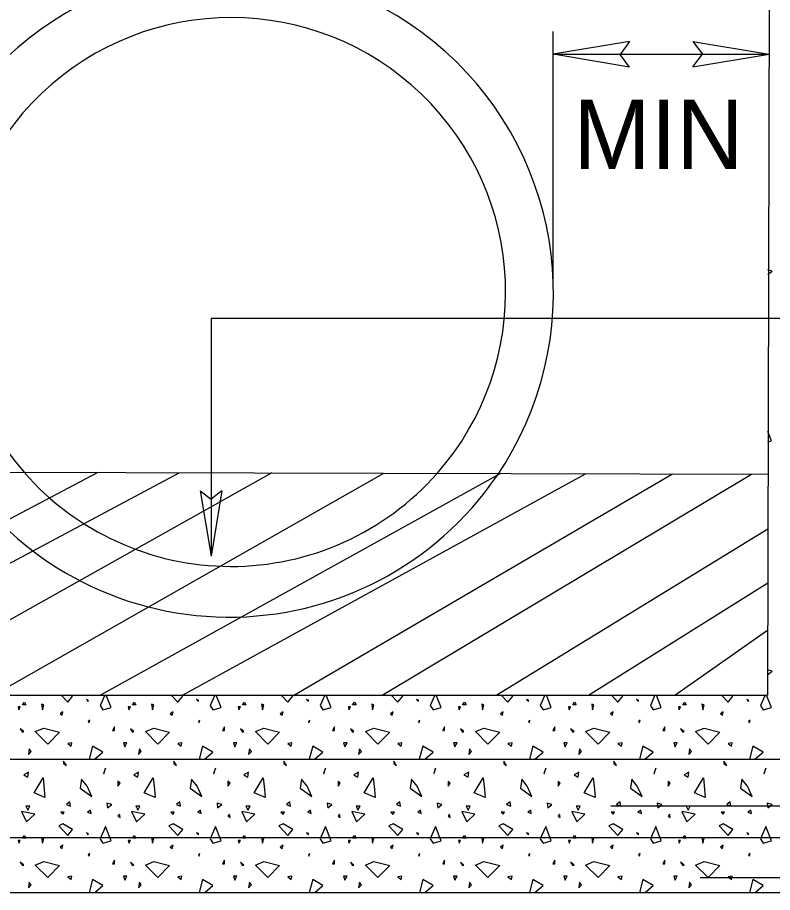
# Model space of a CAD drawing. Extents: x 9.6 to 16.8, y 2.2 to 12.2.
# Drawn here: x 15.328 to 15.979, y 6.99 to 7.746 of the extents above; entities that cross this region are included whole.
import ezdxf

# ---------------------------------------------------------------- set-up
doc = ezdxf.new("R2010")
doc.units = 0
for name, color, linetype in [('DETL-DIMS', 7, 'Continuous'), ('DETL-LINE', 7, 'Continuous'), ('DETL-NOTE', 7, 'Continuous'), ('DETL-PATT', 7, 'Continuous')]:
    doc.layers.add(name, color=color, linetype=linetype)

msp = doc.modelspace()

# ---------------------------------------------------------------- linework, layer by layer
at = {"layer": 'DETL-DIMS'}
for p, q in [((15.79012, 7.51631), (15.79012, 7.73388)), ((15.85604, 7.72498), (15.79012, 7.71412)), ((15.85604, 7.72498), (15.84776, 7.714)), ((15.91067, 7.72522), (15.97651, 7.71412)), ((15.91067, 7.72522), (15.91886, 7.71424)), ((15.79012, 7.71412), (15.97651, 7.71412)), ((15.85596, 7.70302), (15.79012, 7.71412)), ((15.85596, 7.70302), (15.84776, 7.714)), ((15.91059, 7.70325), (15.91886, 7.71424)), ((15.91059, 7.70325), (15.97651, 7.71412)), ((16.21412, 7.48596), (15.49467, 7.48596)), ((15.49467, 7.48596), (15.49467, 7.28039)), ((15.48525, 7.33686), (15.49467, 7.28039)), ((15.48525, 7.33686), (15.49467, 7.3298)), ((15.50408, 7.33686), (15.49467, 7.28039)), ((15.50408, 7.33686), (15.49467, 7.3298))]:
    msp.add_line(p, q, dxfattribs=at)
at = {"layer": 'DETL-LINE'}
for p, q in [((15.9791, 8.70102), (15.97506, 7.16059)), ((15.03792, 7.35373), (15.97557, 7.35125)), ((15.03486, 7.16059), (15.97506, 7.16059)), ((14.98871, 7.10522), (16.01604, 7.10522)), ((15.99635, 7.06451), (15.83973, 7.06451)), ((14.90416, 7.03737), (16.09322, 7.03737)), ((16.07349, 7.00275), (15.91686, 7.00275)), ((14.84702, 6.99), (16.1489, 6.99))]:
    msp.add_line(p, q, dxfattribs=at)
for centre, radius, start, end in [((15.51033, 7.50778), 0.27991, 325.61931, 213.35871), ((15.51198, 7.50873), 0.23705, 318.61489, 221.08317), ((15.51033, 7.50778), 0.27991, 213.35871, 325.61931), ((15.51198, 7.50873), 0.23705, 221.08317, 318.61489)]:
    msp.add_arc(centre, radius, start, end, dxfattribs=at)
at = {"layer": 'DETL-PATT'}
for p, q in [((15.39698, 7.35278), (15.03486, 7.16235)), ((15.10784, 7.16059), (15.46718, 7.35259)), ((15.54729, 7.35239), (15.20498, 7.16059)), ((15.30702, 7.16059), (15.64373, 7.35212)), ((15.74463, 7.35188), (15.39937, 7.16059)), ((15.47004, 7.16059), (15.81784, 7.35169)), ((15.89294, 7.35149), (15.56678, 7.16059)), ((15.64231, 7.16059), (15.96133, 7.35129)), ((15.97545, 7.304), (15.74133, 7.16059)), ((15.82059, 7.16059), (15.97529, 7.25757)), ((15.89498, 7.16059), (15.97522, 7.21659))]:
    msp.add_line(p, q, dxfattribs=at)
for points in [[(15.97549, 7.52384), (15.97898, 7.52678), (15.97549, 7.52776)], [(15.97533, 7.37929), (15.97843, 7.38008), (15.97533, 7.38816)], [(15.9751, 7.18094), (15.97545, 7.1782), (15.97898, 7.18118), (15.9751, 7.18227)], [(15.36525, 7.16059), (15.37094, 7.15451), (15.37518, 7.15973), (15.37369, 7.16059)], [(15.4029, 7.16059), (15.3989, 7.15153), (15.40129, 7.14784), (15.40835, 7.14969), (15.40416, 7.16059)], [(15.46027, 7.16059), (15.46596, 7.15451), (15.4702, 7.15973), (15.46871, 7.16059)], [(15.49792, 7.16059), (15.49392, 7.15153), (15.49631, 7.14784), (15.50337, 7.14969), (15.49918, 7.16059)], [(15.55529, 7.16059), (15.56098, 7.15451), (15.56522, 7.15973), (15.56373, 7.16059)], [(15.5929, 7.16059), (15.58894, 7.15153), (15.59133, 7.14784), (15.59839, 7.14969), (15.59416, 7.16059)], [(15.65031, 7.16059), (15.656, 7.15451), (15.66024, 7.15973), (15.65875, 7.16059)], [(15.68792, 7.16059), (15.68392, 7.15153), (15.68635, 7.14784), (15.69341, 7.14969), (15.68918, 7.16059)], [(15.74529, 7.16059), (15.75098, 7.15451), (15.75522, 7.15973), (15.75373, 7.16059)], [(15.78294, 7.16059), (15.77894, 7.15153), (15.78133, 7.14784), (15.78839, 7.14969), (15.7842, 7.16059)], [(15.84031, 7.16059), (15.846, 7.15451), (15.85024, 7.15973), (15.84875, 7.16059)], [(15.87796, 7.16059), (15.87396, 7.15153), (15.87635, 7.14784), (15.88341, 7.14969), (15.87922, 7.16059)], [(15.93533, 7.16059), (15.94102, 7.15451), (15.94525, 7.15973), (15.94376, 7.16059)], [(15.97298, 7.16059), (15.96898, 7.15153), (15.97137, 7.14784), (15.97843, 7.14969), (15.97424, 7.16059)], [(15.39427, 6.99), (15.40129, 6.99596), (15.39239, 7.00118), (15.38949, 6.99)], [(15.48925, 6.99), (15.49631, 6.99596), (15.48741, 7.00118), (15.48451, 6.99)], [(15.58427, 6.99), (15.59133, 6.99596), (15.58243, 7.00118), (15.57949, 6.99)], [(15.67929, 6.99), (15.68635, 6.99596), (15.67745, 7.00118), (15.67451, 6.99)], [(15.77431, 6.99), (15.78133, 6.99596), (15.77247, 7.00118), (15.76953, 6.99)], [(15.86933, 6.99), (15.87635, 6.99596), (15.86745, 7.00118), (15.86455, 6.99)], [(15.96431, 6.99), (15.97137, 6.99596), (15.96247, 7.00118), (15.95957, 6.99)]]:
    msp.add_lwpolyline(points, dxfattribs=at)
for points in [[(15.33353, 7.15451), (15.33482, 7.15208), (15.33184, 7.15208)], [(15.34835, 7.15267), (15.34906, 7.14784), (15.3502, 7.15208)], [(15.38875, 7.1562), (15.38706, 7.15675), (15.38875, 7.15506)], [(15.42855, 7.15451), (15.4298, 7.15208), (15.42686, 7.15208)], [(15.44337, 7.15267), (15.44408, 7.14784), (15.44522, 7.15208)], [(15.48376, 7.1562), (15.48204, 7.15675), (15.48376, 7.15506)], [(15.52357, 7.15451), (15.52482, 7.15208), (15.52188, 7.15208)], [(15.53839, 7.15267), (15.5391, 7.14784), (15.54024, 7.15208)], [(15.57875, 7.1562), (15.57706, 7.15675), (15.57875, 7.15506)], [(15.61859, 7.15451), (15.61984, 7.15208), (15.61686, 7.15208)], [(15.63341, 7.15267), (15.63412, 7.14784), (15.63522, 7.15208)], [(15.67376, 7.1562), (15.67208, 7.15675), (15.67376, 7.15506)], [(15.71357, 7.15451), (15.71486, 7.15208), (15.71188, 7.15208)], [(15.72839, 7.15267), (15.7291, 7.14784), (15.73024, 7.15208)], [(15.76878, 7.1562), (15.7671, 7.15675), (15.76878, 7.15506)], [(15.80859, 7.15451), (15.80988, 7.15208), (15.8069, 7.15208)], [(15.82341, 7.15267), (15.82412, 7.14784), (15.82525, 7.15208)], [(15.8638, 7.1562), (15.86212, 7.15675), (15.8638, 7.15506)], [(15.90361, 7.15451), (15.90486, 7.15208), (15.90192, 7.15208)], [(15.91843, 7.15267), (15.91914, 7.14784), (15.92027, 7.15208)], [(15.95882, 7.1562), (15.9571, 7.15675), (15.95882, 7.15506)], [(15.32816, 7.15027), (15.32875, 7.14784), (15.33, 7.15027)], [(15.36447, 7.14431), (15.36616, 7.14322), (15.36686, 7.14616)], [(15.42318, 7.15027), (15.42376, 7.14784), (15.42502, 7.15027)], [(15.45945, 7.14431), (15.46118, 7.14322), (15.46188, 7.14616)], [(15.5182, 7.15027), (15.51875, 7.14784), (15.52004, 7.15027)], [(15.55447, 7.14431), (15.55616, 7.14322), (15.55686, 7.14616)], [(15.61322, 7.15027), (15.61376, 7.14784), (15.61506, 7.15027)], [(15.64949, 7.14431), (15.65118, 7.14322), (15.65188, 7.14616)], [(15.70824, 7.15027), (15.70878, 7.14784), (15.71004, 7.15027)], [(15.74451, 7.14431), (15.7462, 7.14322), (15.7469, 7.14616)], [(15.80322, 7.15027), (15.8038, 7.14784), (15.80506, 7.15027)], [(15.83953, 7.14431), (15.84122, 7.14322), (15.84192, 7.14616)], [(15.89824, 7.15027), (15.89882, 7.14784), (15.90008, 7.15027)], [(15.93451, 7.14431), (15.93624, 7.14322), (15.93694, 7.14616)], [(15.39, 7.13898), (15.38875, 7.13784), (15.38945, 7.13655)], [(15.48502, 7.13898), (15.48376, 7.13784), (15.48447, 7.13655)], [(15.58004, 7.13898), (15.57875, 7.13784), (15.57945, 7.13655)], [(15.67506, 7.13898), (15.67376, 7.13784), (15.67447, 7.13655)], [(15.77004, 7.13898), (15.76878, 7.13784), (15.76949, 7.13655)], [(15.86506, 7.13898), (15.8638, 7.13784), (15.86451, 7.13655)], [(15.96008, 7.13898), (15.95882, 7.13784), (15.95953, 7.13655)], [(15.33184, 7.12839), (15.33298, 7.12894), (15.33, 7.13133)], [(15.3502, 7.13192), (15.36388, 7.12839), (15.35373, 7.1182), (15.34298, 7.12894)], [(15.41133, 7.13302), (15.40965, 7.13008), (15.41133, 7.13008)], [(15.42686, 7.12839), (15.428, 7.12894), (15.42502, 7.13133)], [(15.44522, 7.13192), (15.4589, 7.12839), (15.44875, 7.1182), (15.438, 7.12894)], [(15.50635, 7.13302), (15.50463, 7.13008), (15.50635, 7.13008)], [(15.52188, 7.12839), (15.52298, 7.12894), (15.52004, 7.13133)], [(15.54024, 7.13192), (15.55392, 7.12839), (15.54376, 7.1182), (15.53302, 7.12894)], [(15.60133, 7.13302), (15.59965, 7.13008), (15.60133, 7.13008)], [(15.61686, 7.12839), (15.618, 7.12894), (15.61506, 7.13133)], [(15.63522, 7.13192), (15.64894, 7.12839), (15.63875, 7.1182), (15.62804, 7.12894)], [(15.69635, 7.13302), (15.69467, 7.13008), (15.69635, 7.13008)], [(15.71188, 7.12839), (15.71302, 7.12894), (15.71004, 7.13133)], [(15.73024, 7.13192), (15.74392, 7.12839), (15.73376, 7.1182), (15.72306, 7.12894)], [(15.79137, 7.13302), (15.78969, 7.13008), (15.79137, 7.13008)], [(15.8069, 7.12839), (15.80804, 7.12894), (15.80506, 7.13133)], [(15.82525, 7.13192), (15.83894, 7.12839), (15.82878, 7.1182), (15.81804, 7.12894)], [(15.88639, 7.13302), (15.88471, 7.13008), (15.88639, 7.13008)], [(15.90192, 7.12839), (15.90306, 7.12894), (15.90008, 7.13133)], [(15.92027, 7.13192), (15.93396, 7.12839), (15.9238, 7.1182), (15.91306, 7.12894)], [(15.33776, 7.11412), (15.33706, 7.10933), (15.33945, 7.11173)], [(15.37094, 7.11878), (15.37392, 7.11639), (15.37447, 7.11933)], [(15.39412, 7.1051), (15.40129, 7.11114), (15.39239, 7.11639), (15.38945, 7.1051)], [(15.4191, 7.11933), (15.42024, 7.1158), (15.42204, 7.11933)], [(15.43278, 7.11412), (15.43208, 7.10933), (15.43447, 7.11173)], [(15.46596, 7.11878), (15.46894, 7.11639), (15.46949, 7.11933)], [(15.4891, 7.1051), (15.49631, 7.11114), (15.48741, 7.11639), (15.48447, 7.1051)], [(15.51412, 7.11933), (15.51522, 7.1158), (15.51706, 7.11933)], [(15.5278, 7.11412), (15.5271, 7.10933), (15.52949, 7.11173)], [(15.56098, 7.11878), (15.56392, 7.11639), (15.56451, 7.11933)], [(15.58412, 7.1051), (15.59133, 7.11114), (15.58243, 7.11639), (15.57945, 7.1051)], [(15.6091, 7.11933), (15.61024, 7.1158), (15.61208, 7.11933)], [(15.62282, 7.11412), (15.62212, 7.10933), (15.62451, 7.11173)], [(15.656, 7.11878), (15.65894, 7.11639), (15.65953, 7.11933)], [(15.67914, 7.1051), (15.68635, 7.11114), (15.67745, 7.11639), (15.67447, 7.1051)], [(15.70412, 7.11933), (15.70525, 7.1158), (15.7071, 7.11933)], [(15.7178, 7.11412), (15.7171, 7.10933), (15.71953, 7.11173)], [(15.75098, 7.11878), (15.75396, 7.11639), (15.75451, 7.11933)], [(15.77416, 7.1051), (15.78133, 7.11114), (15.77247, 7.11639), (15.76949, 7.1051)], [(15.79914, 7.11933), (15.80027, 7.1158), (15.80212, 7.11933)], [(15.81282, 7.11412), (15.81212, 7.10933), (15.81451, 7.11173)], [(15.846, 7.11878), (15.84898, 7.11639), (15.84953, 7.11933)], [(15.86918, 7.1051), (15.87635, 7.11114), (15.86745, 7.11639), (15.86451, 7.1051)], [(15.89416, 7.11933), (15.89529, 7.1158), (15.8971, 7.11933)], [(15.90784, 7.11412), (15.90714, 7.10933), (15.90953, 7.11173)], [(15.94102, 7.11878), (15.944, 7.11639), (15.94455, 7.11933)], [(15.96416, 7.1051), (15.97137, 7.11114), (15.96247, 7.11639), (15.95953, 7.1051)], [(15.36741, 7.10337), (15.36741, 7.10157), (15.3698, 7.09984)], [(15.40188, 7.09267), (15.40243, 7.09267), (15.40357, 7.09745)], [(15.46243, 7.10337), (15.46243, 7.10157), (15.46482, 7.09984)], [(15.49686, 7.09267), (15.49745, 7.09267), (15.49859, 7.09745)], [(15.55745, 7.10337), (15.55745, 7.10157), (15.55984, 7.09984)], [(15.59188, 7.09267), (15.59247, 7.09267), (15.59357, 7.09745)], [(15.65247, 7.10337), (15.65247, 7.10157), (15.65486, 7.09984)], [(15.6869, 7.09267), (15.68745, 7.09267), (15.68859, 7.09745)], [(15.74745, 7.10337), (15.74745, 7.10157), (15.74988, 7.09984)], [(15.78192, 7.09267), (15.78247, 7.09267), (15.78361, 7.09745)], [(15.84247, 7.10337), (15.84247, 7.10157), (15.84486, 7.09984)], [(15.87694, 7.09267), (15.87749, 7.09267), (15.87863, 7.09745)], [(15.93749, 7.10337), (15.93749, 7.10157), (15.93988, 7.09984)], [(15.97192, 7.09267), (15.97251, 7.09267), (15.97365, 7.09745)], [(15.33298, 7.09153), (15.33651, 7.08969), (15.33706, 7.09392)], [(15.428, 7.09153), (15.43153, 7.08969), (15.43208, 7.09392)], [(15.52298, 7.09153), (15.52651, 7.08969), (15.5271, 7.09392)], [(15.618, 7.09153), (15.62153, 7.08969), (15.62212, 7.09392)], [(15.71302, 7.09153), (15.71655, 7.08969), (15.7171, 7.09392)], [(15.80804, 7.09153), (15.81157, 7.08969), (15.81212, 7.09392)], [(15.90306, 7.09153), (15.90659, 7.08969), (15.90714, 7.09392)], [(15.35075, 7.07898), (15.35133, 7.07192), (15.34188, 7.076), (15.34965, 7.08914)], [(15.38282, 7.08784), (15.38169, 7.08024), (15.39169, 7.07302), (15.38761, 7.08192)], [(15.41427, 7.08616), (15.41427, 7.08192), (15.41612, 7.08431)], [(15.44576, 7.07898), (15.44635, 7.07192), (15.43686, 7.076), (15.44463, 7.08914)], [(15.4778, 7.08784), (15.47671, 7.08024), (15.48671, 7.07302), (15.48263, 7.08192)], [(15.50929, 7.08616), (15.50929, 7.08192), (15.51114, 7.08431)], [(15.54078, 7.07898), (15.54133, 7.07192), (15.53188, 7.076), (15.53965, 7.08914)], [(15.57282, 7.08784), (15.57169, 7.08024), (15.58173, 7.07302), (15.57765, 7.08192)], [(15.60431, 7.08616), (15.60431, 7.08192), (15.60616, 7.08431)], [(15.6358, 7.07898), (15.63635, 7.07192), (15.6269, 7.076), (15.63467, 7.08914)], [(15.66784, 7.08784), (15.66671, 7.08024), (15.67675, 7.07302), (15.67263, 7.08192)], [(15.69933, 7.08616), (15.69933, 7.08192), (15.70118, 7.08431)], [(15.73082, 7.07898), (15.73137, 7.07192), (15.72192, 7.076), (15.72969, 7.08914)], [(15.76286, 7.08784), (15.76173, 7.08024), (15.77176, 7.07302), (15.76765, 7.08192)], [(15.79435, 7.08616), (15.79435, 7.08192), (15.79616, 7.08431)], [(15.8258, 7.07898), (15.82639, 7.07192), (15.81694, 7.076), (15.82471, 7.08914)], [(15.85788, 7.08784), (15.85675, 7.08024), (15.86675, 7.07302), (15.86267, 7.08192)], [(15.88933, 7.08616), (15.88933, 7.08192), (15.89118, 7.08431)], [(15.92082, 7.07898), (15.92141, 7.07192), (15.91192, 7.076), (15.91969, 7.08914)], [(15.95286, 7.08784), (15.95176, 7.08024), (15.96176, 7.07302), (15.95769, 7.08192)], [(15.37278, 7.06839), (15.3698, 7.06596), (15.37333, 7.06471)], [(15.4678, 7.06839), (15.46482, 7.06596), (15.46835, 7.06471)], [(15.56282, 7.06839), (15.55984, 7.06596), (15.56337, 7.06471)], [(15.6578, 7.06839), (15.65486, 7.06596), (15.65839, 7.06471)], [(15.75282, 7.06839), (15.74988, 7.06596), (15.75341, 7.06471)], [(15.84784, 7.06839), (15.84486, 7.06596), (15.84839, 7.06471)], [(15.94286, 7.06839), (15.93988, 7.06596), (15.94341, 7.06471)], [(15.33114, 7.06004), (15.33537, 7.05114), (15.34243, 7.05765)], [(15.33482, 7.06471), (15.33651, 7.06118), (15.33835, 7.06471)], [(15.38816, 7.05949), (15.39114, 7.0582), (15.39059, 7.06118)], [(15.40482, 7.0671), (15.40541, 7.06302), (15.40894, 7.06596)], [(15.42616, 7.06004), (15.43039, 7.05114), (15.43745, 7.05765)], [(15.4298, 7.06471), (15.43153, 7.06118), (15.43333, 7.06471)], [(15.48318, 7.05949), (15.48616, 7.0582), (15.48557, 7.06118)], [(15.49984, 7.0671), (15.50039, 7.06302), (15.50392, 7.06596)], [(15.52118, 7.06004), (15.52541, 7.05114), (15.53247, 7.05765)], [(15.52482, 7.06471), (15.52651, 7.06118), (15.52835, 7.06471)], [(15.5782, 7.05949), (15.58118, 7.0582), (15.58059, 7.06118)], [(15.59486, 7.0671), (15.59541, 7.06302), (15.59894, 7.06596)], [(15.61616, 7.06004), (15.62039, 7.05114), (15.62745, 7.05765)], [(15.61984, 7.06471), (15.62153, 7.06118), (15.62337, 7.06471)], [(15.67322, 7.05949), (15.67616, 7.0582), (15.67561, 7.06118)], [(15.68988, 7.0671), (15.69043, 7.06302), (15.69396, 7.06596)], [(15.71118, 7.06004), (15.71541, 7.05114), (15.72247, 7.05765)], [(15.71486, 7.06471), (15.71655, 7.06118), (15.71839, 7.06471)], [(15.76824, 7.05949), (15.77118, 7.0582), (15.77063, 7.06118)], [(15.78486, 7.0671), (15.78545, 7.06302), (15.78898, 7.06596)], [(15.8062, 7.06004), (15.81043, 7.05114), (15.81749, 7.05765)], [(15.80988, 7.06471), (15.81157, 7.06118), (15.81341, 7.06471)], [(15.86322, 7.05949), (15.8662, 7.0582), (15.86565, 7.06118)], [(15.87988, 7.0671), (15.88047, 7.06302), (15.884, 7.06596)], [(15.90122, 7.06004), (15.90545, 7.05114), (15.91251, 7.05765)], [(15.90486, 7.06471), (15.90659, 7.06118), (15.90839, 7.06471)], [(15.95824, 7.05949), (15.96122, 7.0582), (15.96063, 7.06118)], [(15.9749, 7.0671), (15.97545, 7.06302), (15.97898, 7.06596)], [(15.36502, 7.05949), (15.36686, 7.05765), (15.368, 7.05949)], [(15.41427, 7.0558), (15.41612, 7.05467), (15.41557, 7.05765)], [(15.46004, 7.05949), (15.46188, 7.05765), (15.46298, 7.05949)], [(15.50929, 7.0558), (15.51114, 7.05467), (15.51059, 7.05765)], [(15.55506, 7.05949), (15.55686, 7.05765), (15.558, 7.05949)], [(15.60431, 7.0558), (15.60616, 7.05467), (15.60557, 7.05765)], [(15.65004, 7.05949), (15.65188, 7.05765), (15.65302, 7.05949)], [(15.69933, 7.0558), (15.70118, 7.05467), (15.70059, 7.05765)], [(15.74506, 7.05949), (15.7469, 7.05765), (15.74804, 7.05949)], [(15.79435, 7.0558), (15.79616, 7.05467), (15.79561, 7.05765)], [(15.84008, 7.05949), (15.84192, 7.05765), (15.84306, 7.05949)], [(15.88933, 7.0558), (15.89118, 7.05467), (15.89063, 7.05765)], [(15.9351, 7.05949), (15.93694, 7.05765), (15.93804, 7.05949)], [(15.36318, 7.04761), (15.37094, 7.03929), (15.37518, 7.04451), (15.36686, 7.04933)], [(15.40129, 7.03267), (15.40835, 7.03451), (15.40357, 7.0469), (15.3989, 7.03631)], [(15.4582, 7.04761), (15.46596, 7.03929), (15.4702, 7.04451), (15.46188, 7.04933)], [(15.49631, 7.03267), (15.50337, 7.03451), (15.49859, 7.0469), (15.49392, 7.03631)], [(15.55322, 7.04761), (15.56098, 7.03929), (15.56522, 7.04451), (15.55686, 7.04933)], [(15.59133, 7.03267), (15.59839, 7.03451), (15.59357, 7.0469), (15.58894, 7.03631)], [(15.64824, 7.04761), (15.656, 7.03929), (15.66024, 7.04451), (15.65188, 7.04933)], [(15.68635, 7.03267), (15.69341, 7.03451), (15.68859, 7.0469), (15.68392, 7.03631)], [(15.74322, 7.04761), (15.75098, 7.03929), (15.75522, 7.04451), (15.7469, 7.04933)], [(15.78133, 7.03267), (15.78839, 7.03451), (15.78361, 7.0469), (15.77894, 7.03631)], [(15.83824, 7.04761), (15.846, 7.03929), (15.85024, 7.04451), (15.84192, 7.04933)], [(15.87635, 7.03267), (15.88341, 7.03451), (15.87863, 7.0469), (15.87396, 7.03631)], [(15.93325, 7.04761), (15.94102, 7.03929), (15.94525, 7.04451), (15.93694, 7.04933)], [(15.97137, 7.03267), (15.97843, 7.03451), (15.97365, 7.0469), (15.96898, 7.03631)], [(15.33353, 7.03929), (15.33482, 7.0369), (15.33184, 7.0369)], [(15.34835, 7.03745), (15.34906, 7.03267), (15.3502, 7.0369)], [(15.38875, 7.04098), (15.38706, 7.04157), (15.38875, 7.03984)], [(15.42855, 7.03929), (15.4298, 7.0369), (15.42686, 7.0369)], [(15.44337, 7.03745), (15.44408, 7.03267), (15.44522, 7.0369)], [(15.48376, 7.04098), (15.48204, 7.04157), (15.48376, 7.03984)], [(15.52357, 7.03929), (15.52482, 7.0369), (15.52188, 7.0369)], [(15.53839, 7.03745), (15.5391, 7.03267), (15.54024, 7.0369)], [(15.57875, 7.04098), (15.57706, 7.04157), (15.57875, 7.03984)], [(15.61859, 7.03929), (15.61984, 7.0369), (15.61686, 7.0369)], [(15.63341, 7.03745), (15.63412, 7.03267), (15.63522, 7.0369)], [(15.67376, 7.04098), (15.67208, 7.04157), (15.67376, 7.03984)], [(15.71357, 7.03929), (15.71486, 7.0369), (15.71188, 7.0369)], [(15.72839, 7.03745), (15.7291, 7.03267), (15.73024, 7.0369)], [(15.76878, 7.04098), (15.7671, 7.04157), (15.76878, 7.03984)], [(15.80859, 7.03929), (15.80988, 7.0369), (15.8069, 7.0369)], [(15.82341, 7.03745), (15.82412, 7.03267), (15.82525, 7.0369)], [(15.8638, 7.04098), (15.86212, 7.04157), (15.8638, 7.03984)], [(15.90361, 7.03929), (15.90486, 7.0369), (15.90192, 7.0369)], [(15.91843, 7.03745), (15.91914, 7.03267), (15.92027, 7.0369)], [(15.95882, 7.04098), (15.9571, 7.04157), (15.95882, 7.03984)], [(15.32816, 7.03506), (15.32875, 7.03267), (15.33, 7.03506)], [(15.36447, 7.02914), (15.36616, 7.028), (15.36686, 7.03098)], [(15.42318, 7.03506), (15.42376, 7.03267), (15.42502, 7.03506)], [(15.45945, 7.02914), (15.46118, 7.028), (15.46188, 7.03098)], [(15.5182, 7.03506), (15.51875, 7.03267), (15.52004, 7.03506)], [(15.55447, 7.02914), (15.55616, 7.028), (15.55686, 7.03098)], [(15.61322, 7.03506), (15.61376, 7.03267), (15.61506, 7.03506)], [(15.64949, 7.02914), (15.65118, 7.028), (15.65188, 7.03098)], [(15.70824, 7.03506), (15.70878, 7.03267), (15.71004, 7.03506)], [(15.74451, 7.02914), (15.7462, 7.028), (15.7469, 7.03098)], [(15.80322, 7.03506), (15.8038, 7.03267), (15.80506, 7.03506)], [(15.83953, 7.02914), (15.84122, 7.028), (15.84192, 7.03098)], [(15.89824, 7.03506), (15.89882, 7.03267), (15.90008, 7.03506)], [(15.93451, 7.02914), (15.93624, 7.028), (15.93694, 7.03098)], [(15.39, 7.02376), (15.38875, 7.02263), (15.38945, 7.02137)], [(15.48502, 7.02376), (15.48376, 7.02263), (15.48447, 7.02137)], [(15.58004, 7.02376), (15.57875, 7.02263), (15.57945, 7.02137)], [(15.67506, 7.02376), (15.67376, 7.02263), (15.67447, 7.02137)], [(15.77004, 7.02376), (15.76878, 7.02263), (15.76949, 7.02137)], [(15.86506, 7.02376), (15.8638, 7.02263), (15.86451, 7.02137)], [(15.96008, 7.02376), (15.95882, 7.02263), (15.95953, 7.02137)], [(15.33184, 7.01318), (15.33298, 7.01373), (15.33, 7.01616)], [(15.3502, 7.01671), (15.36388, 7.01318), (15.35373, 7.00302), (15.34298, 7.01373)], [(15.41133, 7.01784), (15.40965, 7.01486), (15.41133, 7.01486)], [(15.42686, 7.01318), (15.428, 7.01373), (15.42502, 7.01616)], [(15.44522, 7.01671), (15.4589, 7.01318), (15.44875, 7.00302), (15.438, 7.01373)], [(15.50635, 7.01784), (15.50463, 7.01486), (15.50635, 7.01486)], [(15.52188, 7.01318), (15.52298, 7.01373), (15.52004, 7.01616)], [(15.54024, 7.01671), (15.55392, 7.01318), (15.54376, 7.00302), (15.53302, 7.01373)], [(15.60133, 7.01784), (15.59965, 7.01486), (15.60133, 7.01486)], [(15.61686, 7.01318), (15.618, 7.01373), (15.61506, 7.01616)], [(15.63522, 7.01671), (15.64894, 7.01318), (15.63875, 7.00302), (15.62804, 7.01373)], [(15.69635, 7.01784), (15.69467, 7.01486), (15.69635, 7.01486)], [(15.71188, 7.01318), (15.71302, 7.01373), (15.71004, 7.01616)], [(15.73024, 7.01671), (15.74392, 7.01318), (15.73376, 7.00302), (15.72306, 7.01373)], [(15.79137, 7.01784), (15.78969, 7.01486), (15.79137, 7.01486)], [(15.8069, 7.01318), (15.80804, 7.01373), (15.80506, 7.01616)], [(15.82525, 7.01671), (15.83894, 7.01318), (15.82878, 7.00302), (15.81804, 7.01373)], [(15.88639, 7.01784), (15.88471, 7.01486), (15.88639, 7.01486)], [(15.90192, 7.01318), (15.90306, 7.01373), (15.90008, 7.01616)], [(15.92027, 7.01671), (15.93396, 7.01318), (15.9238, 7.00302), (15.91306, 7.01373)], [(15.37094, 7.00357), (15.37392, 7.00118), (15.37447, 7.00416)], [(15.4191, 7.00416), (15.42024, 7.00063), (15.42204, 7.00416)], [(15.46596, 7.00357), (15.46894, 7.00118), (15.46949, 7.00416)], [(15.51412, 7.00416), (15.51522, 7.00063), (15.51706, 7.00416)], [(15.56098, 7.00357), (15.56392, 7.00118), (15.56451, 7.00416)], [(15.6091, 7.00416), (15.61024, 7.00063), (15.61208, 7.00416)], [(15.656, 7.00357), (15.65894, 7.00118), (15.65953, 7.00416)], [(15.70412, 7.00416), (15.70525, 7.00063), (15.7071, 7.00416)], [(15.75098, 7.00357), (15.75396, 7.00118), (15.75451, 7.00416)], [(15.79914, 7.00416), (15.80027, 7.00063), (15.80212, 7.00416)], [(15.846, 7.00357), (15.84898, 7.00118), (15.84953, 7.00416)], [(15.89416, 7.00416), (15.89529, 7.00063), (15.8971, 7.00416)], [(15.94102, 7.00357), (15.944, 7.00118), (15.94455, 7.00416)], [(15.33776, 6.9989), (15.33706, 6.99412), (15.33945, 6.99651)], [(15.43278, 6.9989), (15.43208, 6.99412), (15.43447, 6.99651)], [(15.5278, 6.9989), (15.5271, 6.99412), (15.52949, 6.99651)], [(15.62282, 6.9989), (15.62212, 6.99412), (15.62451, 6.99651)], [(15.7178, 6.9989), (15.7171, 6.99412), (15.71953, 6.99651)], [(15.81282, 6.9989), (15.81212, 6.99412), (15.81451, 6.99651)], [(15.90784, 6.9989), (15.90714, 6.99412), (15.90953, 6.99651)]]:
    msp.add_lwpolyline(points, close=True, dxfattribs=at)

# ---------------------------------------------------------------- texts
at = {"layer": 'DETL-NOTE'}
msp.add_text('MIN', height=0.06, dxfattribs=at).set_placement((15.80737, 7.6149))

doc.saveas('drawing.dxf')
